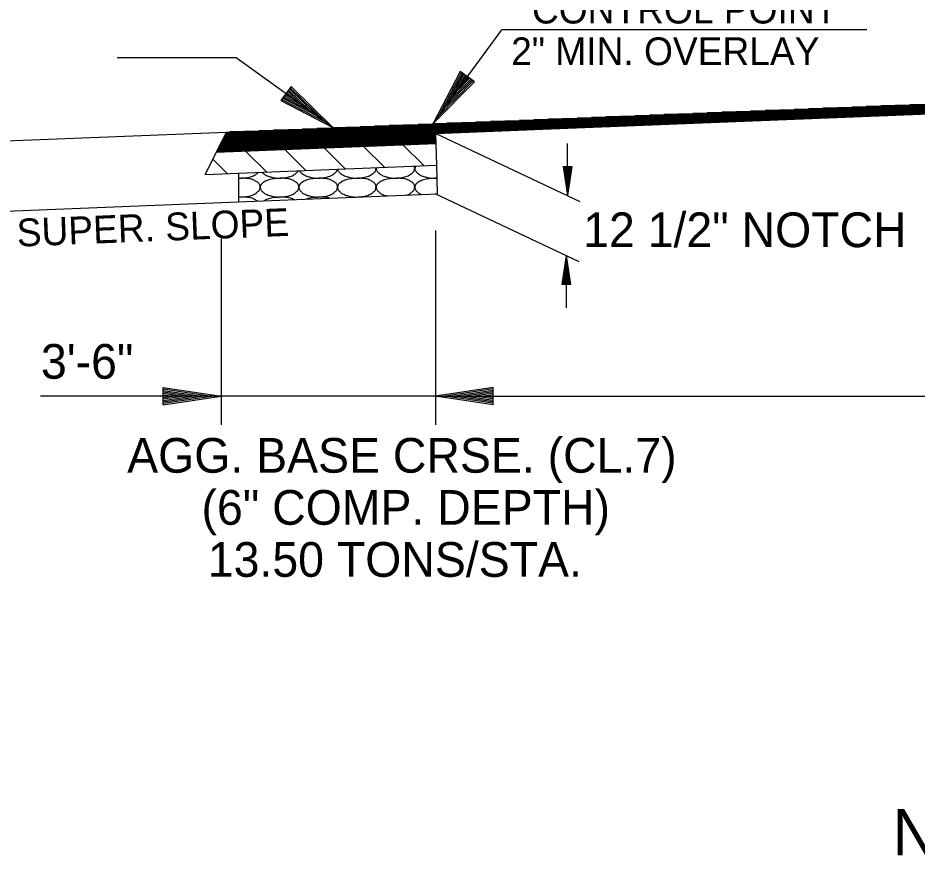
# Model space of a CAD drawing. Extents: x 2263886 to 2266026, y -3122850 to -3121850.
# Drawn here: x 2265578.24 to 2265593.78, y -3122630.63 to -3122616.01 of the extents above; entities that cross this region are included whole.
import ezdxf

# ---------------------------------------------------------------- set-up
doc = ezdxf.new("R2010")
doc.units = 0
doc.layers.add('R_Border Prem', color=7, linetype='Continuous')
doc.layers.add('R_Dimension', color=7, linetype='Continuous')

msp = doc.modelspace()

# ---------------------------------------------------------------- linework, layer by layer
at = {"layer": 'R_Border Prem'}
for p, q in [((2265585.416, -3122617.831), (2265586.602, -3122616.213)), ((2265592.912, -3122616.213), (2265586.602, -3122616.213)), ((2265583.745, -3122617.905), (2265619.716, -3122616.465)), ((2265582.009, -3122616.698), (2265579.95, -3122616.698)), ((2265583.681, -3122617.9), (2265582.009, -3122616.698)), ((2265587.456, -3122617.926), (2265619.723, -3122616.635)), ((2265597.153, -3122617.538), (2265592.9, -3122617.538)), ((2265597.403, -3122617.528), (2265593.15, -3122617.528)), ((2265597.653, -3122617.518), (2265593.4, -3122617.518)), ((2265597.903, -3122617.508), (2265593.65, -3122617.508)), ((2265593.154, -3122617.698), (2265588.901, -3122617.698)), ((2265593.404, -3122617.688), (2265589.151, -3122617.688)), ((2265593.654, -3122617.678), (2265589.401, -3122617.678)), ((2265593.904, -3122617.668), (2265589.651, -3122617.668)), ((2265594.154, -3122617.658), (2265589.901, -3122617.658)), ((2265594.404, -3122617.648), (2265590.151, -3122617.648)), ((2265594.654, -3122617.638), (2265590.401, -3122617.638)), ((2265594.904, -3122617.628), (2265590.651, -3122617.628)), ((2265595.153, -3122617.618), (2265590.901, -3122617.618)), ((2265595.403, -3122617.608), (2265591.151, -3122617.608)), ((2265595.653, -3122617.598), (2265591.401, -3122617.598)), ((2265595.903, -3122617.588), (2265591.651, -3122617.588)), ((2265596.153, -3122617.578), (2265591.901, -3122617.578)), ((2265596.403, -3122617.568), (2265592.151, -3122617.568)), ((2265596.653, -3122617.558), (2265592.401, -3122617.558)), ((2265596.903, -3122617.548), (2265592.651, -3122617.548)), ((2265589.404, -3122617.848), (2265585.152, -3122617.848)), ((2265589.654, -3122617.838), (2265585.402, -3122617.838)), ((2265589.904, -3122617.828), (2265585.652, -3122617.828)), ((2265590.154, -3122617.818), (2265585.902, -3122617.818)), ((2265590.404, -3122617.808), (2265586.152, -3122617.808)), ((2265590.654, -3122617.798), (2265586.402, -3122617.798)), ((2265590.904, -3122617.788), (2265586.652, -3122617.788)), ((2265591.154, -3122617.778), (2265586.901, -3122617.778)), ((2265591.404, -3122617.768), (2265587.151, -3122617.768)), ((2265591.654, -3122617.758), (2265587.401, -3122617.758)), ((2265591.904, -3122617.748), (2265587.651, -3122617.748)), ((2265592.154, -3122617.738), (2265587.901, -3122617.738)), ((2265592.404, -3122617.728), (2265588.151, -3122617.728)), ((2265592.654, -3122617.718), (2265588.401, -3122617.718)), ((2265592.904, -3122617.708), (2265588.651, -3122617.708)), ((2265577.75, -3122618.144), (2265583.745, -3122617.905)), ((2265581.753, -3122618.154), (2265587.456, -3122617.926)), ((2265581.753, -3122618.154), (2265581.84, -3122617.981)), ((2265585.405, -3122618.008), (2265581.826, -3122618.008)), ((2265585.655, -3122617.998), (2265581.831, -3122617.998)), ((2265585.905, -3122617.988), (2265581.836, -3122617.988)), ((2265586.155, -3122617.978), (2265581.902, -3122617.978)), ((2265586.405, -3122617.968), (2265582.152, -3122617.968)), ((2265586.655, -3122617.958), (2265582.402, -3122617.958)), ((2265586.905, -3122617.948), (2265582.652, -3122617.948)), ((2265587.155, -3122617.938), (2265582.902, -3122617.938)), ((2265587.405, -3122617.928), (2265583.152, -3122617.928)), ((2265587.655, -3122617.918), (2265583.402, -3122617.918)), ((2265587.905, -3122617.908), (2265583.652, -3122617.908)), ((2265588.155, -3122617.898), (2265583.902, -3122617.898)), ((2265588.405, -3122617.888), (2265584.152, -3122617.888)), ((2265588.655, -3122617.878), (2265584.402, -3122617.878)), ((2265588.905, -3122617.868), (2265584.652, -3122617.868)), ((2265589.155, -3122617.858), (2265584.902, -3122617.858)), ((2265585.48, -3122618.549), (2265585.458, -3122618.005)), ((2265585.459, -3122618.005), (2265587.947, -3122619.177)), ((2265581.475, -3122618.711), (2265581.753, -3122618.154)), ((2265585.465, -3122618.163), (2265581.749, -3122618.163)), ((2265581.906, -3122618.148), (2265581.756, -3122618.148)), ((2265582.156, -3122618.138), (2265581.761, -3122618.138)), ((2265582.406, -3122618.128), (2265581.766, -3122618.128)), ((2265582.656, -3122618.118), (2265581.771, -3122618.118)), ((2265582.906, -3122618.108), (2265581.776, -3122618.108)), ((2265583.156, -3122618.098), (2265581.781, -3122618.098)), ((2265585.465, -3122618.153), (2265581.781, -3122618.153)), ((2265583.405, -3122618.088), (2265581.786, -3122618.088)), ((2265583.655, -3122618.078), (2265581.791, -3122618.078)), ((2265583.905, -3122618.068), (2265581.796, -3122618.068)), ((2265584.155, -3122618.058), (2265581.801, -3122618.058)), ((2265584.405, -3122618.048), (2265581.806, -3122618.048)), ((2265584.655, -3122618.038), (2265581.811, -3122618.038)), ((2265584.905, -3122618.028), (2265581.816, -3122618.028)), ((2265585.155, -3122618.018), (2265581.821, -3122618.018)), ((2265585.464, -3122618.143), (2265582.031, -3122618.143)), ((2265585.464, -3122618.133), (2265582.281, -3122618.133)), ((2265585.464, -3122618.123), (2265582.531, -3122618.123)), ((2265585.463, -3122618.113), (2265582.781, -3122618.113)), ((2265585.463, -3122618.103), (2265583.031, -3122618.103)), ((2265585.462, -3122618.093), (2265583.281, -3122618.093)), ((2265585.462, -3122618.083), (2265583.531, -3122618.083)), ((2265585.462, -3122618.073), (2265583.781, -3122618.073)), ((2265585.461, -3122618.063), (2265584.031, -3122618.063)), ((2265585.461, -3122618.053), (2265584.281, -3122618.053)), ((2265585.461, -3122618.043), (2265584.531, -3122618.043)), ((2265585.46, -3122618.033), (2265584.781, -3122618.033)), ((2265585.46, -3122618.023), (2265585.031, -3122618.023)), ((2265585.459, -3122618.013), (2265585.281, -3122618.013)), ((2265581.666, -3122618.328), (2265585.465, -3122618.176)), ((2265582.035, -3122618.313), (2265581.674, -3122618.313)), ((2265582.285, -3122618.303), (2265581.679, -3122618.303)), ((2265582.534, -3122618.293), (2265581.684, -3122618.293)), ((2265582.784, -3122618.283), (2265581.689, -3122618.283)), ((2265583.034, -3122618.273), (2265581.694, -3122618.273)), ((2265583.284, -3122618.263), (2265581.699, -3122618.263)), ((2265583.534, -3122618.253), (2265581.704, -3122618.253)), ((2265583.784, -3122618.243), (2265581.709, -3122618.243)), ((2265584.034, -3122618.233), (2265581.714, -3122618.233)), ((2265584.284, -3122618.223), (2265581.719, -3122618.223)), ((2265584.534, -3122618.213), (2265581.724, -3122618.213)), ((2265584.784, -3122618.203), (2265581.729, -3122618.203)), ((2265585.034, -3122618.193), (2265581.734, -3122618.193)), ((2265585.284, -3122618.183), (2265581.739, -3122618.183)), ((2265585.466, -3122618.173), (2265581.744, -3122618.173)), ((2265582.17, -3122618.308), (2265582.531, -3122618.668)), ((2265582.85, -3122618.281), (2265583.211, -3122618.641)), ((2265583.53, -3122618.253), (2265583.891, -3122618.614)), ((2265584.21, -3122618.226), (2265584.571, -3122618.587)), ((2265584.89, -3122618.199), (2265585.25, -3122618.56)), ((2265587.734, -3122619.077), (2265587.734, -3122618.177)), ((2265581.605, -3122618.45), (2265581.851, -3122618.696)), ((2265581.785, -3122618.323), (2265581.669, -3122618.323)), ((2265581.475, -3122618.711), (2265585.48, -3122618.551)), ((2265585.491, -3122619.049), (2265585.48, -3122618.549)), ((2265587.659, -3122618.577), (2265587.734, -3122619.077)), ((2265587.659, -3122618.577), (2265587.809, -3122618.577)), ((2265587.672, -3122618.577), (2265587.734, -3122618.994)), ((2265587.684, -3122618.577), (2265587.734, -3122618.908)), ((2265587.697, -3122618.577), (2265587.734, -3122618.824)), ((2265587.71, -3122618.577), (2265587.734, -3122618.74)), ((2265587.722, -3122618.577), (2265587.734, -3122618.656)), ((2265587.809, -3122618.577), (2265587.734, -3122619.077)), ((2265587.759, -3122618.577), (2265587.734, -3122618.74)), ((2265587.784, -3122618.577), (2265587.734, -3122618.908)), ((2265587.797, -3122618.577), (2265587.734, -3122618.994)), ((2265587.771, -3122618.577), (2265587.734, -3122618.824)), ((2265587.746, -3122618.577), (2265587.734, -3122618.656)), ((2265582.047, -3122618.688), (2265582.047, -3122619.187)), ((2265571.968, -3122619.59), (2265585.491, -3122619.049)), ((2265585.442, -3122619.044), (2265587.93, -3122620.216)), ((2265585.452, -3122619.683), (2265585.452, -3122622.544)), ((2265581.75, -3122619.823), (2265581.75, -3122623.044)), ((2265587.642, -3122620.616), (2265587.717, -3122620.116)), ((2265587.717, -3122621.016), (2265587.717, -3122620.116)), ((2265587.792, -3122620.616), (2265587.717, -3122620.116)), ((2265587.655, -3122620.616), (2265587.717, -3122620.199)), ((2265587.667, -3122620.616), (2265587.717, -3122620.285)), ((2265587.78, -3122620.616), (2265587.717, -3122620.199)), ((2265587.767, -3122620.616), (2265587.717, -3122620.285)), ((2265587.68, -3122620.616), (2265587.717, -3122620.368)), ((2265587.693, -3122620.616), (2265587.717, -3122620.453)), ((2265587.754, -3122620.616), (2265587.717, -3122620.368)), ((2265587.741, -3122620.616), (2265587.717, -3122620.453)), ((2265587.792, -3122620.616), (2265587.642, -3122620.616)), ((2265587.705, -3122620.616), (2265587.717, -3122620.537)), ((2265587.729, -3122620.616), (2265587.717, -3122620.537)), ((2265580.75, -3122622.394), (2265581.75, -3122622.544)), ((2265580.75, -3122622.694), (2265580.75, -3122622.394)), ((2265580.75, -3122622.419), (2265581.583, -3122622.544)), ((2265580.75, -3122622.445), (2265581.411, -3122622.544)), ((2265580.75, -3122622.47), (2265581.244, -3122622.544)), ((2265580.75, -3122622.495), (2265581.075, -3122622.544)), ((2265586.452, -3122622.394), (2265585.452, -3122622.544)), ((2265586.452, -3122622.419), (2265585.619, -3122622.544)), ((2265586.452, -3122622.445), (2265585.791, -3122622.544)), ((2265586.452, -3122622.47), (2265585.957, -3122622.544)), ((2265586.452, -3122622.495), (2265586.127, -3122622.544)), ((2265586.452, -3122622.694), (2265586.452, -3122622.394)), ((2265585.452, -3122622.544), (2265578.629, -3122622.544)), ((2265580.75, -3122622.521), (2265580.908, -3122622.544)), ((2265580.75, -3122622.694), (2265581.75, -3122622.544)), ((2265580.75, -3122622.593), (2265581.075, -3122622.544)), ((2265580.75, -3122622.644), (2265581.411, -3122622.544)), ((2265580.75, -3122622.669), (2265581.583, -3122622.544)), ((2265580.75, -3122622.619), (2265581.244, -3122622.544)), ((2265580.75, -3122622.568), (2265580.908, -3122622.544)), ((2265585.452, -3122622.544), (2265618.122, -3122622.544)), ((2265586.452, -3122622.694), (2265585.452, -3122622.544)), ((2265585.452, -3122622.544), (2265585.452, -3122623.044)), ((2265586.452, -3122622.669), (2265585.619, -3122622.544)), ((2265586.452, -3122622.644), (2265585.791, -3122622.544)), ((2265586.452, -3122622.619), (2265585.957, -3122622.544)), ((2265586.452, -3122622.593), (2265586.127, -3122622.544)), ((2265586.452, -3122622.521), (2265586.294, -3122622.544)), ((2265586.452, -3122622.568), (2265586.294, -3122622.544))]:
    msp.add_line(p, q, dxfattribs=at)
for points in [[(2265583.102, -3122618.646), (2265583.104, -3122618.65), (2265583.11, -3122618.661), (2265583.126, -3122618.681), (2265583.15, -3122618.695), (2265583.166, -3122618.718), (2265583.193, -3122618.724), (2265583.227, -3122618.744), (2265583.289, -3122618.76), (2265583.37, -3122618.777), (2265583.465, -3122618.776), (2265583.563, -3122618.762), (2265583.653, -3122618.738), (2265583.712, -3122618.692), (2265583.752, -3122618.657), (2265583.757, -3122618.63), (2265583.758, -3122618.619)], [(2265583.76, -3122618.619), (2265583.76, -3122618.623), (2265583.766, -3122618.637), (2265583.775, -3122618.657), (2265583.794, -3122618.681), (2265583.818, -3122618.695), (2265583.834, -3122618.718), (2265583.861, -3122618.724), (2265583.895, -3122618.744), (2265583.957, -3122618.76), (2265584.038, -3122618.777), (2265584.132, -3122618.776), (2265584.231, -3122618.762), (2265584.32, -3122618.738), (2265584.38, -3122618.692), (2265584.422, -3122618.656), (2265584.426, -3122618.62), (2265584.427, -3122618.6), (2265584.426, -3122618.593)], [(2265584.433, -3122618.592), (2265584.431, -3122618.6), (2265584.423, -3122618.613), (2265584.433, -3122618.636), (2265584.443, -3122618.657), (2265584.462, -3122618.681), (2265584.486, -3122618.695), (2265584.502, -3122618.718), (2265584.529, -3122618.724), (2265584.563, -3122618.744), (2265584.625, -3122618.76), (2265584.706, -3122618.777), (2265584.8, -3122618.776), (2265584.899, -3122618.762), (2265584.988, -3122618.738), (2265585.048, -3122618.692), (2265585.089, -3122618.656), (2265585.094, -3122618.617), (2265585.095, -3122618.589), (2265585.091, -3122618.572), (2265585.089, -3122618.566)], [(2265585.109, -3122618.565), (2265585.109, -3122618.567), (2265585.106, -3122618.575), (2265585.101, -3122618.591), (2265585.091, -3122618.612), (2265585.101, -3122618.636), (2265585.11, -3122618.657), (2265585.129, -3122618.681), (2265585.154, -3122618.695), (2265585.17, -3122618.718), (2265585.196, -3122618.724), (2265585.231, -3122618.744), (2265585.293, -3122618.76), (2265585.373, -3122618.777), (2265585.441, -3122618.776), (2265585.478, -3122618.773), (2265585.485, -3122618.772)], [(2265582.047, -3122618.775), (2265582.074, -3122618.776), (2265582.133, -3122618.775), (2265582.227, -3122618.762), (2265582.317, -3122618.738), (2265582.367, -3122618.699), (2265582.39, -3122618.679), (2265582.396, -3122618.674)], [(2265582.047, -3122619.101), (2265582.074, -3122619.102), (2265582.133, -3122619.101), (2265582.227, -3122619.089), (2265582.317, -3122619.065), (2265582.376, -3122619.018), (2265582.418, -3122618.982), (2265582.423, -3122618.944), (2265582.423, -3122618.91), (2265582.416, -3122618.882), (2265582.399, -3122618.863), (2265582.382, -3122618.846), (2265582.356, -3122618.835), (2265582.333, -3122618.817), (2265582.301, -3122618.805), (2265582.261, -3122618.785), (2265582.195, -3122618.781), (2265582.124, -3122618.777), (2265582.073, -3122618.78), (2265582.05, -3122618.782), (2265582.047, -3122618.782)], [(2265582.45, -3122618.874), (2265582.444, -3122618.879), (2265582.436, -3122618.894), (2265582.43, -3122618.918), (2265582.419, -3122618.938), (2265582.43, -3122618.962), (2265582.439, -3122618.984), (2265582.458, -3122619.007), (2265582.483, -3122619.022), (2265582.498, -3122619.045), (2265582.525, -3122619.05), (2265582.559, -3122619.07), (2265582.622, -3122619.087), (2265582.702, -3122619.104), (2265582.797, -3122619.102), (2265582.895, -3122619.089), (2265582.985, -3122619.065), (2265583.044, -3122619.018), (2265583.086, -3122618.982), (2265583.091, -3122618.944), (2265583.091, -3122618.91), (2265583.083, -3122618.882), (2265583.067, -3122618.863), (2265583.049, -3122618.846), (2265583.023, -3122618.835), (2265583.001, -3122618.817), (2265582.969, -3122618.805), (2265582.928, -3122618.785), (2265582.862, -3122618.781), (2265582.792, -3122618.777), (2265582.721, -3122618.783), (2265582.667, -3122618.784), (2265582.62, -3122618.797), (2265582.575, -3122618.804), (2265582.532, -3122618.82), (2265582.492, -3122618.841), (2265582.467, -3122618.862), (2265582.449, -3122618.874), (2265582.444, -3122618.88)], [(2265582.45, -3122618.672), (2265582.452, -3122618.674), (2265582.463, -3122618.684), (2265582.483, -3122618.695), (2265582.498, -3122618.718), (2265582.525, -3122618.724), (2265582.559, -3122618.744), (2265582.622, -3122618.76), (2265582.702, -3122618.777), (2265582.797, -3122618.776), (2265582.895, -3122618.762), (2265582.985, -3122618.738), (2265583.044, -3122618.692), (2265583.075, -3122618.666), (2265583.083, -3122618.647), (2265583.084, -3122618.646)], [(2265583.118, -3122618.874), (2265583.112, -3122618.879), (2265583.104, -3122618.894), (2265583.098, -3122618.918), (2265583.087, -3122618.938), (2265583.097, -3122618.962), (2265583.107, -3122618.984), (2265583.126, -3122619.007), (2265583.15, -3122619.022), (2265583.166, -3122619.045), (2265583.193, -3122619.05), (2265583.227, -3122619.07), (2265583.289, -3122619.087), (2265583.37, -3122619.104), (2265583.465, -3122619.102), (2265583.563, -3122619.089), (2265583.653, -3122619.065), (2265583.712, -3122619.018), (2265583.754, -3122618.982), (2265583.758, -3122618.944), (2265583.759, -3122618.91), (2265583.751, -3122618.882), (2265583.735, -3122618.863), (2265583.717, -3122618.846), (2265583.691, -3122618.835), (2265583.669, -3122618.817), (2265583.637, -3122618.805), (2265583.596, -3122618.785), (2265583.53, -3122618.781), (2265583.46, -3122618.777), (2265583.389, -3122618.783), (2265583.335, -3122618.784), (2265583.288, -3122618.797), (2265583.243, -3122618.804), (2265583.2, -3122618.82), (2265583.16, -3122618.841), (2265583.134, -3122618.862), (2265583.116, -3122618.874), (2265583.112, -3122618.88)], [(2265583.786, -3122618.874), (2265583.78, -3122618.879), (2265583.772, -3122618.894), (2265583.766, -3122618.918), (2265583.755, -3122618.938), (2265583.765, -3122618.962), (2265583.775, -3122618.984), (2265583.794, -3122619.007), (2265583.818, -3122619.022), (2265583.834, -3122619.045), (2265583.861, -3122619.05), (2265583.895, -3122619.07), (2265583.957, -3122619.087), (2265584.038, -3122619.104), (2265584.132, -3122619.102), (2265584.231, -3122619.089), (2265584.32, -3122619.065), (2265584.38, -3122619.018), (2265584.422, -3122618.982), (2265584.426, -3122618.944), (2265584.427, -3122618.91), (2265584.419, -3122618.882), (2265584.403, -3122618.863), (2265584.385, -3122618.846), (2265584.359, -3122618.835), (2265584.337, -3122618.817), (2265584.304, -3122618.805), (2265584.264, -3122618.785), (2265584.198, -3122618.781), (2265584.128, -3122618.777), (2265584.057, -3122618.783), (2265584.003, -3122618.784), (2265583.956, -3122618.797), (2265583.911, -3122618.804), (2265583.867, -3122618.82), (2265583.828, -3122618.841), (2265583.802, -3122618.862), (2265583.784, -3122618.874), (2265583.78, -3122618.88)], [(2265584.952, -3122619.07), (2265584.966, -3122619.066), (2265585.003, -3122619.053), (2265585.048, -3122619.018), (2265585.089, -3122618.982), (2265585.094, -3122618.944), (2265585.095, -3122618.91), (2265585.087, -3122618.882), (2265585.071, -3122618.863), (2265585.053, -3122618.846), (2265585.027, -3122618.835), (2265585.005, -3122618.817), (2265584.972, -3122618.805), (2265584.932, -3122618.785), (2265584.866, -3122618.781), (2265584.796, -3122618.777), (2265584.725, -3122618.783), (2265584.671, -3122618.784), (2265584.624, -3122618.797), (2265584.578, -3122618.804), (2265584.535, -3122618.82), (2265584.496, -3122618.841), (2265584.47, -3122618.862), (2265584.452, -3122618.874), (2265584.448, -3122618.88)], [(2265585.485, -3122618.778), (2265585.475, -3122618.777), (2265585.445, -3122618.778), (2265585.393, -3122618.783), (2265585.339, -3122618.784), (2265585.292, -3122618.797), (2265585.246, -3122618.804), (2265585.203, -3122618.82), (2265585.164, -3122618.841), (2265585.138, -3122618.862), (2265585.12, -3122618.874), (2265585.116, -3122618.88)], [(2265584.454, -3122618.874), (2265584.447, -3122618.879), (2265584.44, -3122618.894), (2265584.433, -3122618.918), (2265584.423, -3122618.938), (2265584.433, -3122618.962), (2265584.443, -3122618.984), (2265584.462, -3122619.007), (2265584.486, -3122619.022), (2265584.502, -3122619.045), (2265584.529, -3122619.05), (2265584.563, -3122619.07), (2265584.595, -3122619.079), (2265584.616, -3122619.084), (2265584.616, -3122619.084)], [(2265585.122, -3122618.874), (2265585.115, -3122618.879), (2265585.108, -3122618.894), (2265585.101, -3122618.918), (2265585.091, -3122618.938), (2265585.101, -3122618.962), (2265585.11, -3122618.984), (2265585.129, -3122619.007), (2265585.154, -3122619.022), (2265585.17, -3122619.045), (2265585.192, -3122619.048), (2265585.204, -3122619.056), (2265585.212, -3122619.06)], [(2265582.381, -3122619.173), (2265582.374, -3122619.169), (2265582.355, -3122619.161), (2265582.333, -3122619.143), (2265582.301, -3122619.131), (2265582.261, -3122619.112), (2265582.195, -3122619.107), (2265582.124, -3122619.103), (2265582.073, -3122619.107), (2265582.05, -3122619.108), (2265582.047, -3122619.108)], [(2265583.01, -3122619.148), (2265583.006, -3122619.146), (2265582.995, -3122619.141), (2265582.969, -3122619.131), (2265582.928, -3122619.112), (2265582.862, -3122619.107), (2265582.792, -3122619.103), (2265582.721, -3122619.109), (2265582.667, -3122619.11), (2265582.62, -3122619.123), (2265582.575, -3122619.13), (2265582.532, -3122619.146), (2265582.504, -3122619.161), (2265582.493, -3122619.168), (2265582.492, -3122619.169)], [(2265583.616, -3122619.124), (2265583.611, -3122619.122), (2265583.586, -3122619.111), (2265583.53, -3122619.107), (2265583.46, -3122619.103), (2265583.389, -3122619.109), (2265583.335, -3122619.11), (2265583.288, -3122619.123), (2265583.252, -3122619.129), (2265583.228, -3122619.137), (2265583.22, -3122619.14)]]:
    msp.add_open_spline(points, degree=3, dxfattribs=at)
at = {"layer": 'R_Dimension'}
for p, q in [((2265585.883, -3122616.934), (2265585.416, -3122617.831)), ((2265585.903, -3122616.948), (2265585.514, -3122617.696)), ((2265585.924, -3122616.963), (2265585.616, -3122617.556)), ((2265585.944, -3122616.978), (2265585.713, -3122617.422)), ((2265586.064, -3122617.066), (2265585.713, -3122617.422)), ((2265585.965, -3122616.993), (2265585.813, -3122617.285)), ((2265586.043, -3122617.05), (2265585.813, -3122617.285)), ((2265586.126, -3122617.11), (2265585.883, -3122616.934)), ((2265585.985, -3122617.008), (2265585.911, -3122617.15)), ((2265586.023, -3122617.036), (2265585.911, -3122617.15)), ((2265582.959, -3122617.192), (2265582.783, -3122617.435)), ((2265582.93, -3122617.233), (2265583.407, -3122617.701)), ((2265582.945, -3122617.212), (2265583.546, -3122617.802)), ((2265582.959, -3122617.192), (2265583.681, -3122617.9)), ((2265586.126, -3122617.11), (2265585.416, -3122617.831)), ((2265586.105, -3122617.095), (2265585.514, -3122617.696)), ((2265586.085, -3122617.08), (2265585.616, -3122617.556)), ((2265582.828, -3122617.374), (2265583.272, -3122617.603)), ((2265582.842, -3122617.353), (2265583.134, -3122617.504)), ((2265582.857, -3122617.332), (2265582.999, -3122617.406)), ((2265582.885, -3122617.294), (2265582.999, -3122617.406)), ((2265582.9, -3122617.274), (2265583.134, -3122617.504)), ((2265582.915, -3122617.253), (2265583.272, -3122617.603)), ((2265582.783, -3122617.435), (2265583.681, -3122617.9)), ((2265582.798, -3122617.415), (2265583.546, -3122617.802)), ((2265582.813, -3122617.394), (2265583.407, -3122617.701))]:
    msp.add_line(p, q, dxfattribs=at)

# ---------------------------------------------------------------- texts
at = {"layer": 'R_Border Prem'}
for s, height, p in [('CONTROL POINT', 0.48, (2265587.121, -3122616.102)), ('2" MIN. OVERLAY', 0.48, (2265586.762, -3122616.822)), ('12 1/2" NOTCH', 0.6, (2265588.006, -3122619.969)), ('3\'-6"', 0.6, (2265578.635, -3122622.244)), ('AGG. BASE CRSE. (CL.7)', 0.6, (2265580.125, -3122623.869)), ('(6" COMP. DEPTH)', 0.6, (2265581.41, -3122624.769)), ('13.50 TONS/STA.', 0.6, (2265581.519, -3122625.669)), ('NOTCH, WIDEN, AND OVERLAY ', 0.8, (2265593.353, -3122630.486))]:
    msp.add_text(s, height=height, dxfattribs=at).set_placement(p)
msp.add_text('SUPER. SLOPE', height=0.48, rotation=2.291, dxfattribs=at).set_placement((2265578.226, -3122619.961))

doc.saveas('drawing.dxf')
